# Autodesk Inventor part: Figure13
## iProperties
Shininess: 77.0
Length Units: 11269
Angle Units: 11279
Time Units: 11290
Mass Units: 11283
Length Display Precision: 3
Angle Display Precision: 2
Created: 2002-01
Part Number: Figure13
Document SubType Name: Modeling
Designer: ***
Density: 0.0
Volumn: 0.0
Area: 0.0
PropertySet Name: Model Information
Control State: 0
Master: False
Checked Out: False
Author: ***
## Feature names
1. Extrusion2
